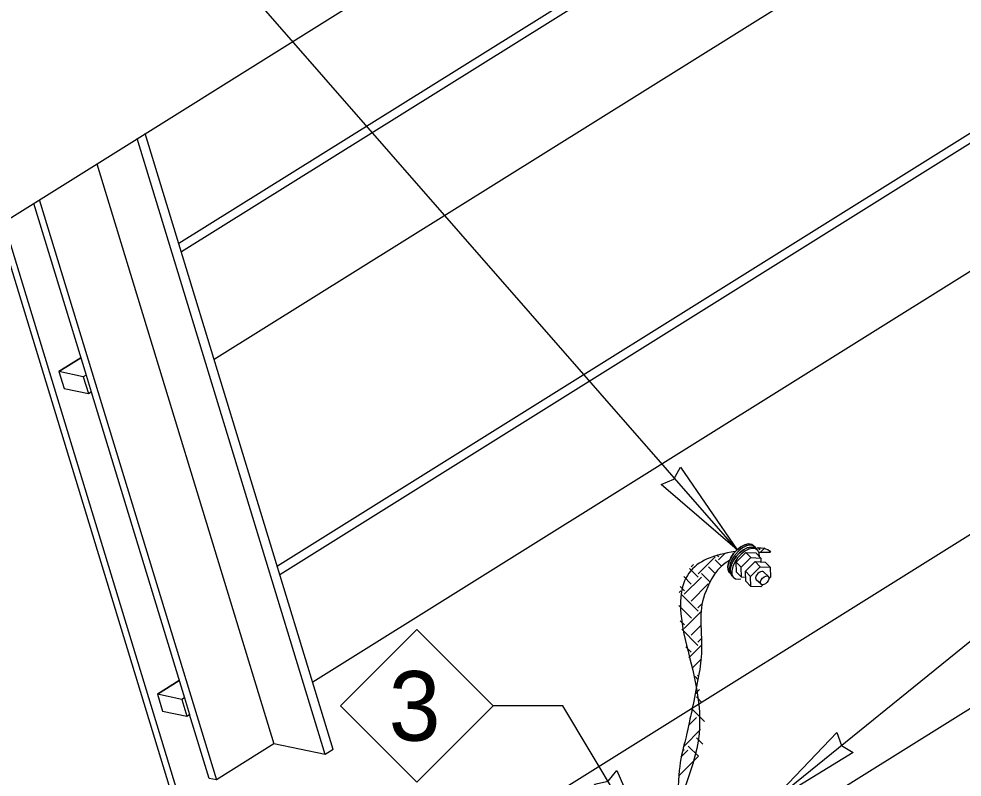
# Model space of a CAD drawing. Extents: x 99862 to 103151, y 100000 to 105076.
# Drawn here: x 100286.8 to 100503.6, y 100888.1 to 101062.4 of the extents above; entities that cross this region are included whole.
import ezdxf

# ---------------------------------------------------------------- set-up
doc = ezdxf.new("R2010")
doc.units = 0
for name, color, linetype in [('Level 1', 7, 'Continuous'), ('Level 15', 7, 'Continuous'), ('Level 20', 7, 'Continuous'), ('Level 4', 7, 'Continuous'), ('Level 5', 7, 'Continuous')]:
    doc.layers.add(name, color=color, linetype=linetype)

msp = doc.modelspace()

# ---------------------------------------------------------------- linework, layer by layer
at = {"layer": 'Level 1'}
for p, q in [((100518.2, 101132.42), (100323.56, 101010.78)), ((100521, 101131.83), (100324.15, 101008.82)), ((100540.84, 101058.24), (100346.19, 100936.6)), ((100543.64, 101057.65), (100346.79, 100934.64)), ((100295.98, 100981.32), (100301.01, 100984.46)), ((100302.21, 100980.54), (100303.39, 100976.68)), ((100301.58, 100980.15), (100302.76, 100976.28)), ((100553.1, 100973.63), (100354.56, 100849.56)), ((100381.31, 100826.39), (100557.03, 100936.2)), ((100318.61, 100907.14), (100323.65, 100910.28)), ((100324.21, 100905.97), (100318.61, 100907.14)), ((100324.84, 100906.36), (100326.02, 100902.5))]:
    msp.add_line(p, q, dxfattribs=at)
for points in [[(100528.55, 101107.11), (100528.55, 101107.11), (100331.7, 100984.09)], [(100357.16, 100893.27), (100313.95, 101034.89)], [(100359.05, 100894.45), (100315.84, 101036.07)], [(100551.18, 101032.93), (100551.18, 101032.93), (100354.33, 100909.91)], [(100304.7, 101029.11), (100345.41, 100895.73)], [(100290.16, 101020.03), (100302.21, 100980.54)], [(100291.48, 101020.85), (100332.18, 100887.47)], [(100324.27, 100881.42), (100283.29, 101015.73)], [(100281.97, 101014.91), (100322.59, 100881.77)], [(100301.01, 100984.46), (100295.98, 100981.32), (100297.16, 100977.45), (100297.16, 100977.45)], [(100295.98, 100981.32), (100297.16, 100977.45), (100302.76, 100976.28), (100303.39, 100976.68), (100324.84, 100906.36)], [(100302.21, 100980.54), (100301.58, 100980.15), (100295.98, 100981.32)], [(100456.33, 100940.42), (100456.1, 100940.92), (100455.58, 100941.31), (100454.86, 100941.42), (100454.02, 100941.24), (100453.12, 100940.79), (100452.23, 100940.1), (100451.42, 100939.24), (100450.76, 100938.26), (100450.31, 100937.25), (100450.09, 100936.29), (100450.13, 100935.47), (100450.33, 100935.04)], [(100456.99, 100938.8), (100456.95, 100939.55), (100456.66, 100940.19), (100456.13, 100940.57), (100455.42, 100940.68), (100454.58, 100940.5), (100453.67, 100940.05), (100452.78, 100939.37), (100451.97, 100938.5), (100451.32, 100937.53), (100450.86, 100936.52), (100450.65, 100935.56), (100450.69, 100934.73), (100450.98, 100934.1), (100451.51, 100933.71), (100452.22, 100933.6), (100452.7, 100933.7)], [(100323.65, 100910.28), (100318.61, 100907.14), (100319.79, 100903.28), (100319.79, 100903.28)], [(100318.61, 100907.14), (100319.79, 100903.28), (100325.39, 100902.1), (100326.02, 100902.5)], [(100324.84, 100906.36), (100324.21, 100905.97), (100325.39, 100902.1)], [(100359.05, 100894.45), (100357.16, 100893.27), (100345.41, 100895.73), (100332.18, 100887.47), (100330.5, 100887.82), (100326.02, 100902.5)]]:
    msp.add_lwpolyline(points, dxfattribs=at)
at = {"layer": 'Level 15'}
for p, q in [((100451.87, 100940.39), (100310.35, 101102.24)), ((100458.92, 100881.7), (100656.15, 101041.32)), ((100411.79, 100904.47), (100395.79, 100904.47)), ((100433.44, 100868.5), (100411.79, 100904.47))]:
    msp.add_line(p, q, dxfattribs=at)
msp.add_lwpolyline([(100267.92, 101006.13), (100390.2, 101082.54), (100396.76, 101072.03), (100404.64, 101106.18), (100411.21, 101095.67), (100533.48, 101172.08)], dxfattribs=at)
for points in [[(100451.87, 100940.39), (100434.42, 100955.41), (100437.35, 100956.61), (100438.87, 100959.39)], [(100458.92, 100881.7), (100474.79, 100898.38), (100475.84, 100895.39), (100478.54, 100893.74)], [(100433.44, 100868.5), (100419.11, 100886.52), (100422.21, 100887.15), (100424.22, 100889.6)]]:
    msp.add_lwpolyline(points, close=True, dxfattribs=at)
at = {"layer": 'Level 20'}
msp.add_lwpolyline([(100378.24, 100922.03), (100360.68, 100904.47), (100378.24, 100886.92), (100395.79, 100904.47)], close=True, dxfattribs=at)
at = {"layer": 'Level 4'}
for p, q in [((100454.51, 100941.71), (100453.67, 100941.53)), ((100455.22, 100941.6), (100454.51, 100941.71)), ((100447.59, 100938.02), (100449.13, 100939.56)), ((100451.67, 100937.54), (100453.89, 100939.75)), ((100455.05, 100938.56), (100453.89, 100939.75)), ((100453.89, 100939.75), (100456.18, 100939.65)), ((100455.07, 100940.97), (100454.22, 100940.79)), ((100455.78, 100940.86), (100455.07, 100940.97)), ((100457.34, 100938.46), (100456.18, 100939.65)), ((100456.6, 100940.87), (100457.09, 100940.39)), ((100457.27, 100939.84), (100458.26, 100940.83)), ((100442.9, 100934.85), (100446.84, 100938.78)), ((100446.86, 100938.03), (100448.23, 100936.66)), ((100447.2, 100939.2), (100447.62, 100938.78)), ((100451.76, 100935.25), (100451.67, 100937.54)), ((100452.83, 100936.35), (100451.67, 100937.54)), ((100452.83, 100936.35), (100455.05, 100938.56)), ((100453.8, 100935.44), (100456.02, 100937.64)), ((100455.05, 100938.56), (100457.34, 100938.46)), ((100457.18, 100936.45), (100456.02, 100937.64)), ((100456.02, 100937.64), (100458.31, 100937.54)), ((100457.34, 100938.46), (100457.36, 100937.58)), ((100459.47, 100936.35), (100458.31, 100937.54)), ((100440.9, 100936.07), (100442.9, 100934.07)), ((100441.33, 100936.42), (100441.86, 100936.96)), ((100443.72, 100934.88), (100445.54, 100933.06)), ((100445.29, 100936.45), (100446.7, 100935.05)), ((100452.91, 100934.05), (100451.76, 100935.25)), ((100452.91, 100934.05), (100452.83, 100936.35)), ((100453.89, 100933.14), (100453.8, 100935.44)), ((100454.96, 100934.24), (100453.8, 100935.44)), ((100454.96, 100934.25), (100457.18, 100936.45)), ((100457.18, 100936.45), (100459.47, 100936.35)), ((100459.47, 100936.35), (100459.54, 100934.06)), ((100439.59, 100934.23), (100441.33, 100932.49)), ((100439.73, 100930.16), (100443.66, 100934.09)), ((100453.86, 100934.02), (100452.91, 100934.05)), ((100455.04, 100931.95), (100453.89, 100933.14)), ((100455.04, 100931.95), (100454.96, 100934.24)), ((100459.54, 100934.06), (100459.2, 100933.72)), ((100438.58, 100930.53), (100438.97, 100930.92)), ((100438.78, 100931.9), (100439.76, 100930.92)), ((100441.3, 100928.59), (100445.24, 100932.52)), ((100457.33, 100931.86), (100455.04, 100931.95)), ((100457.78, 100932.31), (100457.33, 100931.86)), ((100439, 100930.16), (100442.93, 100926.23)), ((100438.5, 100927.52), (100441.36, 100924.66)), ((100442.88, 100927.02), (100443.69, 100927.83)), ((100438.82, 100924.06), (100439.79, 100923.09)), ((100439.73, 100922.3), (100443.52, 100926.09)), ((100439.14, 100922.11), (100442.88, 100918.37)), ((100441.3, 100920.73), (100443.51, 100922.94)), ((100442.88, 100919.16), (100443.68, 100919.96)), ((100440.07, 100918.03), (100441.3, 100916.8)), ((100440.78, 100915.54), (100443.64, 100918.4)), ((100443.69, 100919.18), (100443.73, 100919.15)), ((100441.54, 100913.15), (100443.65, 100915.26)), ((100442.2, 100911.24), (100442.86, 100910.58)), ((100442.85, 100911.32), (100443.03, 100911.51)), ((100442.23, 100907.2), (100443.25, 100908.22)), ((100442.5, 100906.53), (100443.76, 100905.28)), ((100441.53, 100903.74), (100444.41, 100900.86)), ((100440.7, 100900.01), (100442.5, 100901.82)), ((100439.67, 100895.21), (100443.48, 100899.02)), ((100442.54, 100897.13), (100443.96, 100895.71)), ((100438.97, 100892.68), (100440.58, 100894.3)), ((100439.38, 100894.56), (100439.67, 100894.27)), ((100440.65, 100895.25), (100442.98, 100892.92)), ((100438.39, 100888.33), (100442.98, 100892.92))]:
    msp.add_line(p, q, dxfattribs=at)
for points in [[(100450.4, 100934.85), (100450.08, 100935.12), (100449.78, 100935.76), (100449.74, 100936.58), (100449.95, 100937.54), (100450.41, 100938.55), (100451.07, 100939.53), (100451.87, 100940.39), (100452.76, 100941.08), (100453.67, 100941.53), (100454.51, 100941.71), (100455.22, 100941.6), (100455.75, 100941.21)], [(100453.67, 100941.53), (100452.76, 100941.08), (100451.87, 100940.39)], [(100455.75, 100941.21), (100455.75, 100941.21), (100455.22, 100941.6)], [(100451.87, 100940.39), (100451.07, 100939.53), (100450.41, 100938.55), (100449.95, 100937.54), (100449.74, 100936.58), (100449.78, 100935.76), (100450.08, 100935.12), (100450.08, 100935.12)], [(100450.96, 100934.12), (100450.63, 100934.39), (100450.34, 100935.02), (100450.29, 100935.85), (100450.51, 100936.81), (100450.96, 100937.82), (100451.62, 100938.79), (100452.43, 100939.66), (100453.32, 100940.34), (100454.22, 100940.79), (100455.07, 100940.97), (100455.78, 100940.86), (100456.3, 100940.48)], [(100452.43, 100939.66), (100451.62, 100938.79), (100450.96, 100937.82), (100450.51, 100936.81), (100450.29, 100935.85), (100450.34, 100935.02), (100450.63, 100934.39), (100450.63, 100934.39)], [(100454.22, 100940.79), (100453.32, 100940.34), (100452.43, 100939.66)], [(100456.3, 100940.48), (100456.3, 100940.48), (100455.78, 100940.86)]]:
    msp.add_lwpolyline(points, dxfattribs=at)
for points in [[(100451.46, 100939.95), (100446.44, 100939.16), (100439.26, 100936.58), (100437.74, 100923.23), (100447.63, 100896.58), (100429.16, 100868.61), (100436.94, 100808.16), (100440.35, 100786.44)], [(100456.18, 100940.75), (100456.91, 100941), (100458.99, 100940.78), (100459.57, 100939.83)], [(100456.83, 100939.82), (100457.28, 100939.85), (100458.94, 100939.83), (100459.57, 100939.83)], [(100450.12, 100937.92), (100447.26, 100936.4), (100444.04, 100930.18), (100443.31, 100925.31), (100443.94, 100916.76), (100443.1, 100911.78), (100441.69, 100904.37), (100440.55, 100899.48), (100440.55, 100898.73), (100438.77, 100892.51), (100438.09, 100885.24), (100438.09, 100861.72), (100439.26, 100849.28), (100444.73, 100798.95), (100446.55, 100782.34)]]:
    msp.add_open_spline(points, degree=3, dxfattribs=at)
at = {"layer": 'Level 5'}
for p, q in [((100457.96, 100935.27), (100459.06, 100934.23)), ((100457.37, 100932.43), (100456.26, 100933.47))]:
    msp.add_line(p, q, dxfattribs=at)
for start_param, end_param in [(3.676158, 6.283241), (3.14158, 3.676158)]:
    msp.add_ellipse((100457.11, 100934.37), major_axis=(-0.848, -0.901), ratio=0.57735, start_param=start_param, end_param=end_param, dxfattribs=at)
msp.add_ellipse((100458.21, 100933.33), major_axis=(0.848, 0.901), ratio=0.57735, dxfattribs=at)

# ---------------------------------------------------------------- texts
at = {"layer": 'Level 20'}
msp.add_text('3', height=16, dxfattribs=at).set_placement((100371.79, 100896.48))

doc.saveas('drawing.dxf')
